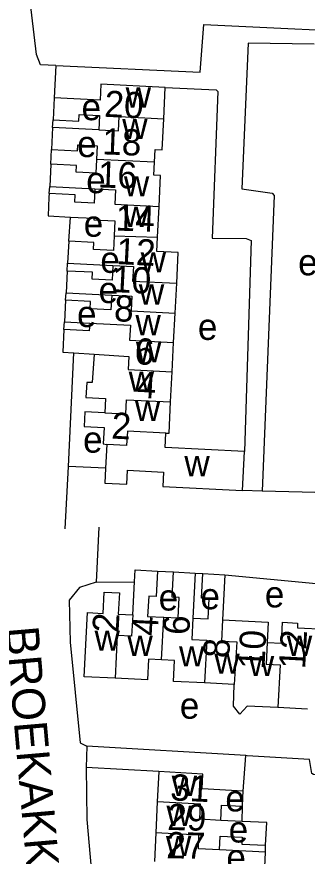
# Model space of a CAD drawing. Extents: x 163026 to 166241, y 382475 to 384501.
# Drawn here: x 164331.2 to 164375.5, y 383742 to 383869.8 of the extents above; entities that cross this region are included whole.
import ezdxf

# ---------------------------------------------------------------- set-up
doc = ezdxf.new("R2010")
doc.units = 0
for name, color, linetype in [('BLT_Basislijn', 7, 'Continuous'), ('BLT_Bebouwing', 7, 'Continuous'), ('BLT_Centroide', 7, 'Continuous'), ('BLT_Huisnummer', 7, 'Continuous'), ('BLT_Huisnummer_ tussenligend', 7, 'Continuous'), ('BLT_Onderverdeling_panden', 7, 'Continuous'), ('BLT_Straatnaam', 7, 'Continuous')]:
    doc.layers.add(name, color=color, linetype=linetype)

msp = doc.modelspace()

# ---------------------------------------------------------------- linework, layer by layer
at = {"layer": 'BLT_Basislijn'}
for p, q in [((164337.16, 383862.36), (164336.92, 383857.45)), ((164336.67, 383852.92), (164336.75, 383854.08)), ((164336.42, 383847.34), (164336.5, 383849.56)), ((164336.14, 383842.86), (164336.24, 383843.97)), ((164339.13, 383835.63), (164339.41, 383839.29)), ((164338.91, 383831.08), (164338.96, 383832.26)), ((164338.65, 383826.64), (164338.74, 383827.75)), ((164338.4, 383822.15), (164338.48, 383823.32)), ((164339.08, 383801.3), (164339.89, 383818.6)), ((164338.57, 383791.84), (164339.08, 383801.3)), ((164344.73, 383801.05), (164339.08, 383801.3)), ((164368.58, 383797.56), (164365.62, 383797.64)), ((164343.7, 383792.08), (164343.33, 383783.68)), ((164352.66, 383785.38), (164355.07, 383785.27)), ((164358.4, 383785.09), (164359.55, 383785.01)), ((164343.33, 383783.68), (164349.14, 383783.73)), ((164341.86, 383758.72), (164341.78, 383755.48)), ((164366.09, 383757.3), (164341.86, 383758.72)), ((164365.69, 383751.88), (164366.09, 383757.3)), ((164352.83, 383754.87), (164341.78, 383755.48)), ((164365.54, 383747.27), (164365.58, 383749.6)), ((164369.09, 383742.59), (164369.12, 383743.63))]:
    msp.add_line(p, q, dxfattribs=at)
for points in [[(164337.16, 383862.36), (164334.83, 383862.48), (164334.21, 383864.03), (164331.61, 383885.95), (164332.01, 383888.94), (164332.65, 383889.98), (164334.68, 383891.6)], [(164337.16, 383862.36), (164359.15, 383861.36), (164359.72, 383868.62), (164389.59, 383867.19)], [(164376.53, 383865.62), (164366.45, 383865.76), (164365.49, 383843.58), (164370.09, 383842.96), (164370.41, 383842.58), (164368.58, 383797.56)], [(164353.84, 383859.02), (164361.6, 383858.65), (164361.86, 383858.43), (164361, 383836.06), (164366.17, 383836.01), (164366.94, 383835.75), (164365.92, 383803.58)], [(164389.59, 383790.87), (164377.38, 383795.23), (164376.74, 383797.34), (164368.58, 383797.56)], [(164343.33, 383783.68), (164340.79, 383782.9), (164339.17, 383780.94), (164339.36, 383774.54), (164340.89, 383759.22), (164341.86, 383758.72)], [(164362.91, 383784.83), (164376.82, 383783.48), (164376.82, 383780.37), (164383.07, 383779.95), (164382.85, 383777.09)], [(164386.96, 383763.76), (164386.46, 383754.76), (164386.19, 383753.96), (164376.43, 383754.44), (164376.18, 383754.57), (164375.82, 383756.7), (164366.33, 383757.28), (164366.09, 383757.3)], [(164341.78, 383755.48), (164341.89, 383747.55), (164344.79, 383714.89), (164344.95, 383709.95), (164344.23, 383699.4), (164342.12, 383690.8), (164340.37, 383685.18)]]:
    msp.add_lwpolyline(points, dxfattribs=at)
at = {"layer": 'BLT_Bebouwing'}
for p, q in [((164353.6, 383854.25), (164353.84, 383859.02)), ((164336.92, 383857.45), (164336.75, 383854.08)), ((164336.67, 383852.92), (164336.5, 383849.56)), ((164336.42, 383847.34), (164336.24, 383843.97)), ((164352.65, 383836.21), (164352.88, 383840.9)), ((164339.13, 383835.63), (164338.96, 383832.26)), ((164338.91, 383831.08), (164338.74, 383827.75)), ((164355.34, 383824.68), (164355.57, 383829.22)), ((164338.65, 383826.64), (164338.48, 383823.32)), ((164355.11, 383820.18), (164355.34, 383824.68)), ((164338.48, 383823.32), (164342.32, 383823.12)), ((164354.89, 383815.72), (164355.11, 383820.18)), ((164354.65, 383811.16), (164354.89, 383815.72)), ((164344.91, 383804.65), (164344.73, 383801.05)), ((164365.62, 383797.64), (164365.92, 383803.58)), ((164355.07, 383785.27), (164358.4, 383785.09)), ((164359.55, 383785.01), (164362.91, 383784.83)), ((164364.31, 383768.12), (164359.83, 383768.36)), ((164375.49, 383764.36), (164371, 383764.6)), ((164352.61, 383750.25), (164352.38, 383745.55)), ((164352.38, 383745.55), (164352.17, 383741.15)), ((164368.93, 383739.21), (164369.09, 383742.59))]:
    msp.add_line(p, q, dxfattribs=at)
for points in [[(164353.84, 383859.02), (164344.02, 383859.52), (164343.9, 383857.1), (164336.92, 383857.45)], [(164336.75, 383854.08), (164340.65, 383853.88), (164340.71, 383854.9), (164343.8, 383854.74), (164343.69, 383852.56)], [(164352.2, 383847.63), (164352.3, 383849.58), (164353.36, 383849.53), (164353.6, 383854.25)], [(164343.69, 383852.56), (164336.67, 383852.92)], [(164336.5, 383849.56), (164340.47, 383849.36), (164340.52, 383850.3), (164343.47, 383850.15), (164343.37, 383848.08)], [(164343.37, 383848.08), (164343.26, 383845.97), (164340.26, 383846.12), (164340.31, 383847.15), (164336.42, 383847.34)], [(164352.88, 383840.9), (164353.12, 383845.63), (164352.11, 383845.68), (164352.2, 383847.63)], [(164336.24, 383843.97), (164343.12, 383843.62)], [(164336.14, 383842.86), (164336.11, 383842.31), (164335.97, 383839.47), (164339.41, 383839.29)], [(164343.12, 383843.62), (164343.01, 383841.41), (164340.05, 383841.56), (164340.11, 383842.66), (164336.14, 383842.86)], [(164339.41, 383839.29), (164342.97, 383839.11), (164342.96, 383838.87), (164346.13, 383838.71), (164346.05, 383836.46)], [(164346.05, 383836.46), (164345.97, 383834.21), (164342.92, 383834.36), (164342.97, 383835.44), (164339.13, 383835.63)], [(164355.57, 383829.22), (164355.81, 383833.88), (164352.54, 383834.05), (164352.65, 383836.21)], [(164338.96, 383832.26), (164345.86, 383831.91)], [(164345.86, 383831.91), (164345.74, 383829.7), (164342.72, 383829.86), (164342.77, 383830.89), (164338.91, 383831.08)], [(164345.68, 383827.4), (164345.56, 383825.18), (164342.41, 383825.34), (164342.46, 383826.45), (164338.65, 383826.64)], [(164338.74, 383827.75), (164345.68, 383827.4)], [(164338.4, 383822.15), (164338.23, 383818.71), (164339.89, 383818.6)], [(164342.32, 383823.12), (164342.26, 383821.96), (164338.4, 383822.15)], [(164339.89, 383818.6), (164343.02, 383818.4)], [(164343.02, 383818.4), (164342.72, 383814.09), (164341.86, 383814.13), (164341.74, 383811.8), (164344.75, 383811.65), (164344.64, 383809.5)], [(164353.93, 383806.4), (164354.41, 383806.37), (164354.65, 383811.16)], [(164344.64, 383809.5), (164341.6, 383809.65), (164341.49, 383807.4), (164344.5, 383807.25), (164344.38, 383804.75), (164344.91, 383804.65)], [(164365.92, 383803.58), (164353.82, 383804.19), (164353.93, 383806.4)], [(164344.73, 383801.05), (164344.61, 383798.8), (164347.96, 383798.63), (164348.07, 383800.74), (164353.58, 383800.46), (164353.46, 383798.26), (164365.62, 383797.64)], [(164349.14, 383783.73), (164349.24, 383785.56), (164352.66, 383785.38)], [(164352.66, 383785.38), (164352.46, 383781.51), (164351.31, 383781.57), (164351.15, 383778.49), (164353.61, 383778.36)], [(164353.61, 383778.36), (164355.81, 383778.25), (164355.97, 383781.35), (164354.87, 383781.41), (164355.07, 383785.27)], [(164358.4, 383785.09), (164358.05, 383778.24)], [(164358.05, 383778.24), (164360.35, 383778.12), (164360.51, 383781.2), (164359.35, 383781.26), (164359.55, 383785.01)], [(164348.88, 383778.72), (164349.14, 383783.73)], [(164362.91, 383784.83), (164362.56, 383777.99)], [(164346.19, 383769.06), (164341.48, 383769.31), (164341.99, 383779.07), (164344.37, 383778.95), (164344.54, 383782.18), (164346.85, 383782.06), (164346.68, 383778.83), (164348.88, 383778.72)], [(164362.56, 383777.99), (164369.53, 383777.63), (164369.37, 383774.53)], [(164369.37, 383774.53), (164371.53, 383774.42), (164371.7, 383777.59), (164373.99, 383777.47), (164373.96, 383776.75), (164378.3, 383776.53)], [(164353.27, 383771.89), (164351.28, 383771.99), (164351.12, 383768.81), (164346.19, 383769.06)], [(164359.83, 383768.36), (164355.1, 383768.6), (164355.26, 383771.78), (164353.27, 383771.89)], [(164371, 383764.6), (164366.29, 383764.84), (164365.17, 383763.61), (164364.21, 383764.81), (164364.31, 383768.12)], [(164352.83, 383754.87), (164352.61, 383750.25)], [(164365.69, 383751.88), (164359.46, 383752.25), (164359.56, 383754.49), (164352.83, 383754.87)], [(164365.58, 383749.6), (164365.6, 383750), (164365.69, 383751.88)], [(164362.28, 383747.43), (164362.39, 383749.76), (164365.58, 383749.6)], [(164365.54, 383747.27), (164362.28, 383747.43)], [(164369.12, 383743.63), (164369.29, 383747.09), (164365.54, 383747.27)], [(164362.08, 383742.93), (164362.18, 383745.04), (164365.53, 383744.88), (164365.48, 383743.81), (164369.12, 383743.63)], [(164369.09, 383742.59), (164362.08, 383742.93)]]:
    msp.add_lwpolyline(points, dxfattribs=at)
at = {"layer": 'BLT_Onderverdeling_panden'}
for p, q in [((164352.2, 383847.63), (164343.37, 383848.08)), ((164346.05, 383836.46), (164352.65, 383836.21)), ((164348.17, 383816.06), (164354.89, 383815.72)), ((164353.27, 383771.89), (164353.61, 383778.36))]:
    msp.add_line(p, q, dxfattribs=at)
for points in [[(164343.69, 383852.56), (164346.71, 383852.41), (164346.83, 383854.59), (164353.6, 383854.25)], [(164343.12, 383843.62), (164346.24, 383843.46), (164346.13, 383841.25), (164352.88, 383840.9)], [(164345.86, 383831.91), (164348.97, 383831.75), (164348.86, 383829.55), (164355.57, 383829.22)], [(164345.68, 383827.4), (164348.74, 383827.24), (164348.63, 383825.02), (164355.34, 383824.68)], [(164342.32, 383823.12), (164348.52, 383822.81), (164348.4, 383820.53), (164355.11, 383820.18)], [(164343.02, 383818.4), (164348.27, 383818.07), (164348.17, 383816.06)], [(164344.64, 383809.5), (164347.83, 383809.34), (164347.94, 383811.49), (164354.65, 383811.16)], [(164353.93, 383806.4), (164348.06, 383806.71), (164347.95, 383804.49), (164344.91, 383804.65)], [(164348.88, 383778.72), (164348.7, 383775.46), (164346.52, 383775.58), (164346.19, 383769.06)], [(164358.05, 383778.24), (164357.88, 383774.98), (164360.18, 383774.86), (164359.83, 383768.36)], [(164362.56, 383777.99), (164362.39, 383774.74), (164364.75, 383774.62), (164364.31, 383768.12)], [(164369.37, 383774.53), (164369.2, 383771.23), (164371.35, 383771.12), (164371, 383764.6)], [(164362.28, 383747.43), (164359.08, 383747.59), (164359.19, 383749.92), (164352.61, 383750.25)], [(164362.08, 383742.93), (164358.87, 383743.08), (164358.97, 383745.2), (164352.38, 383745.55)]]:
    msp.add_lwpolyline(points, dxfattribs=at)

# ---------------------------------------------------------------- texts
at = {"layer": 'BLT_Centroide'}
for s, p in [('w', (164347.8, 383855.97)), ('e', (164341.08, 383854.04)), ('w', (164347.27, 383851.16)), ('e', (164340.4, 383848.43)), ('e', (164341.79, 383842.93)), ('w', (164347.53, 383842.44)), ('w', (164347.45, 383837.79)), ('e', (164341.41, 383836.3)), ('e', (164343.94, 383830.8)), ('w', (164350.08, 383830.87)), ('e', (164374.07, 383830.42)), ('e', (164343.67, 383826.2)), ('w', (164349.81, 383825.96)), ('e', (164340.39, 383822.55)), ('w', (164349.29, 383821.31)), ('e', (164358.8, 383820.59)), ('w', (164349.37, 383817.19)), ('w', (164348.26, 383812.69)), ('w', (164349.22, 383808.24)), ('e', (164341.31, 383803.42)), ('w', (164356.74, 383799.83)), ('e', (164352.82, 383779.38)), ('e', (164359.19, 383779.57)), ('e', (164369, 383779.86)), ('w', (164343.06, 383773.26)), ('w', (164348.06, 383772.47)), ('w', (164372.35, 383772.47)), ('w', (164355.93, 383770.86)), ('w', (164361.31, 383769.75)), ('w', (164366.56, 383769.4)), ('e', (164356.05, 383762.91)), ('w', (164354.81, 383751.16)), ('e', (164362.98, 383748.79)), ('w', (164354.02, 383746.59)), ('e', (164363.49, 383744.06)), ('w', (164353.93, 383742)), ('e', (164363.14, 383739.8))]:
    msp.add_text(s, height=4, dxfattribs=at).set_placement(p)
at = {"layer": 'BLT_Huisnummer'}
for s, rotation, p in [('20', 357.0915, (164344.49, 383854.58)), ('14', 357.8895, (164346.22, 383837.25)), ('10', 357.092, (164345.65, 383827.89)), ('6', 357.0707, (164349.09, 383816.9)), ('2', 357.0905, (164345.56, 383805.58)), ('2', 87.0118, (164346.71, 383775.94)), ('6', 87.0118, (164357.48, 383775.59)), ('10', 87.0118, (164368.93, 383770.38)), ('31', 357.215, (164354.53, 383750.5))]:
    msp.add_text(s, height=4, rotation=rotation, dxfattribs=at).set_placement(p)
at = {"layer": 'BLT_Huisnummer_ tussenligend'}
for s, rotation, p in [('18', 357.8895, (164344.18, 383848.85)), ('16', 357.8895, (164343.51, 383843.82)), ('12', 357.092, (164346.31, 383832.15)), ('8', 357.0707, (164345.96, 383823.46)), ('4', 357.0905, (164349.41, 383811.79)), ('4', 87.0118, (164352.66, 383775.45)), ('12', 87.0118, (164375.13, 383770.4)), ('8', 87.0118, (164363.57, 383772.08)), ('29', 358.6481, (164354.1, 383745.98)), ('27', 358.6481, (164353.95, 383741.68))]:
    msp.add_text(s, height=4, rotation=rotation, dxfattribs=at).set_placement(p)
at = {"layer": 'BLT_Straatnaam'}
msp.add_text('BROEKAKKERSEWEG', height=5, rotation=274.9501, dxfattribs=at).set_placement((164329.52, 383776.79))

doc.saveas('drawing.dxf')
